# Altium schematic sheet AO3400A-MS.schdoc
size 127 x 101 mm
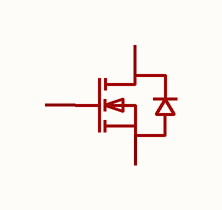
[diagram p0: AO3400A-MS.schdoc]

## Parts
Q?  ao3400a-ms  [SOT-23-3_L2.9-W1.3-P1.90-LS2.4-BR]  (value not drawn)

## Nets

Not connected (* = marked no-connect by the designer): Q? 1(G) 2(S) 3(D)

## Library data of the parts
Q? = ao3400a-ms: 数量:1个N沟道;漏源电压(Vdss):30V;连续漏极电流(Id):5.8A;导通电阻(RDS(on)):20mΩ@10V;耗散功率(Pd):1.56W;阈值电压(Vgs(th)):900mV;; Manufacturer: MSKSEMI(美森科); AddInBom: yes; ModelId: c62791f0466c4ae2a892c056b845b0ca; ModelName: SOT-23-3P_L2.9-W1.3-H1.0-LS2.4-P0.95; ModelTransform: 98.425,114.173,0,180,0,0,0.0005,-0.0005,0; Number: 1个N沟道; Drain to Source Voltage: 30V; Current - Continuous Drain(Id): 5.8A; Pd - Power Dissipation: 1.56W; Gate Threshold Voltage (Vgs(th)): 900mV; Gate Charge(Qg): 8.4nC@4.5V; Input Capacitance(Ciss): 695pF; Reverse Transfer Capacitance (Crss@Vds): 36pF; Output Capacitance(Coss): 45pF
